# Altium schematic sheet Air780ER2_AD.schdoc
size 208 x 137 mm
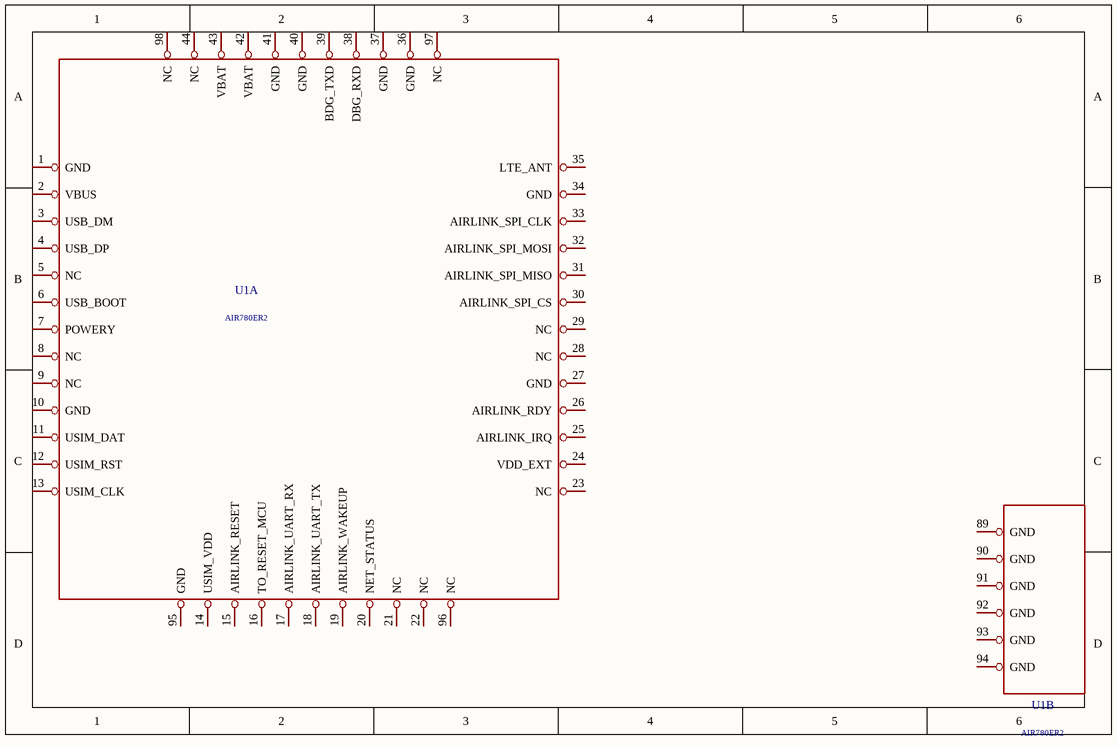
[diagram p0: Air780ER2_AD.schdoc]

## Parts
U1  AIR780ER2  (parts A,B of 2)

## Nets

Not connected (* = marked no-connect by the designer): U1 1(GND) 2(VBUS) 3(USB_DM) 4(USB_DP) 5(NC) 6(USB_BOOT) 7(POWERY) 8(NC) 9(NC) 10(GND) 11(USIM_DAT) 12(USIM_RST) 13(USIM_CLK) 14(USIM_VDD) 15(AIRLINK_RESET) 16(TO_RESET_MCU) 17(AIRLINK_UART_RX) 18(AIRLINK_UART_TX) 19(AIRLINK_WAKEUP) 20(NET_STATUS) 21(NC) 22(NC) 23(NC) 24(VDD_EXT) 25(AIRLINK_IRQ) 26(AIRLINK_RDY) 27(GND) 28(NC) 29(NC) 30(AIRLINK_SPI_CS) 31(AIRLINK_SPI_MISO) 32(AIRLINK_SPI_MOSI) 33(AIRLINK_SPI_CLK) 34(GND) 35(LTE_ANT) 36(GND) 37(GND) 38(DBG_RXD) 39(BDG_TXD) 40(GND) 41(GND) 42(VBAT) 43(VBAT) 44(NC) 89(GND) 90(GND) 91(GND) 92(GND) 93(GND) 94(GND) 95(GND) 96(NC) 97(NC) 98(NC)

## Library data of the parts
U1 = AIR780ER2: Add into BOM: yes; Origin Footprint: AIR780EX2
